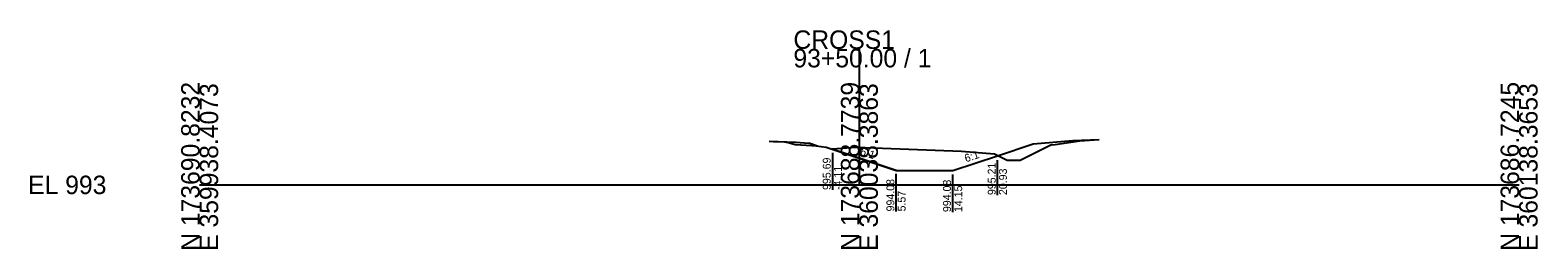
# Model space of a CAD drawing. Extents: x -26 to 1403, y -10 to 11027.
# Drawn here: x -25.7 to 202.8, y 8490.3 to 8523.5 of the extents above; entities that cross this region are included whole.
import ezdxf

# ---------------------------------------------------------------- set-up
doc = ezdxf.new("R2010")
doc.units = 0
for name, color, linetype in [('Default', 7, 'Continuous'), ('P_E_XS_Ground', 7, 'Continuous'), ('P_XS', 7, 'Continuous'), ('P_XS_EAR_CommonGrnd', 7, 'Continuous'), ('P_XS_Lane', 7, 'Continuous'), ('P_XS_Rock', 7, 'Continuous')]:
    doc.layers.add(name, color=color, linetype=linetype)

msp = doc.modelspace()

# ---------------------------------------------------------------- linework, layer by layer
at = {"layer": 'Default'}
for p, q in [((100, 8500), (100, 8520.61)), ((0, 8500), (100, 8500)), ((100, 8500), (200, 8500))]:
    msp.add_line(p, q, dxfattribs=at)
at = {"layer": 'P_E_XS_Ground'}
for p, q in [((86.35, 8506.63), (86.97, 8506.57)), ((86.97, 8506.57), (88.66, 8506.55)), ((88.66, 8506.55), (89.41, 8506.37)), ((89.41, 8506.37), (90.27, 8506.13)), ((90.27, 8506.13), (92.8, 8505.99)), ((92.8, 8505.99), (93.46, 8505.9)), ((129.12, 8506.07), (124.38, 8503.7)), ((129.12, 8506.07), (129.69, 8506.14)), ((129.69, 8506.14), (133.43, 8506.66)), ((133.43, 8506.66), (135.61, 8506.82)), ((135.61, 8506.82), (136.34, 8506.87)), ((93.46, 8505.9), (94.98, 8505.72)), ((94.98, 8505.72), (95.89, 8505.39)), ((99.5, 8505.68), (95.89, 8505.39)), ((115.5, 8505.04), (99.5, 8505.68)), ((120.5, 8504.64), (115.5, 8505.04)), ((122.38, 8503.7), (120.5, 8504.64)), ((124.38, 8503.7), (122.38, 8503.7))]:
    msp.add_line(p, q, dxfattribs=at)
at = {"layer": 'P_XS'}
for p, q in [((86.35, 8506.63), (90.35, 8506.47)), ((90.35, 8506.47), (92.35, 8506.31)), ((93.64, 8505.88), (92.35, 8506.31)), ((120.93, 8504.42), (126.35, 8506.23)), ((126.35, 8506.23), (132.35, 8506.71)), ((132.35, 8506.71), (136.35, 8506.87))]:
    msp.add_line(p, q, dxfattribs=at)
at = {"layer": 'P_XS_EAR_CommonGrnd'}
msp.add_lwpolyline([(114.15, 8502.16), (120.93, 8504.42), (120.5, 8504.64), (115.5, 8505.04), (99.5, 8505.68), (95.89, 8505.39), (105.57, 8502.16)], close=True, dxfattribs=at)
at = {"layer": 'P_XS_Lane'}
for p, q in [((105.57, 8502.16), (95.89, 8505.39)), ((114.15, 8502.16), (120.93, 8504.42)), ((105.57, 8502.16), (114.15, 8502.16))]:
    msp.add_line(p, q, dxfattribs=at)
at = {"layer": 'P_XS_Rock'}
for p, q in [((95.9, 8504.84), (95.9, 8499.23)), ((120.91, 8503.77), (120.91, 8498.46)), ((105.55, 8501.68), (105.55, 8495.97)), ((114.13, 8501.59), (114.13, 8495.88))]:
    msp.add_line(p, q, dxfattribs=at)

# ---------------------------------------------------------------- texts
at = {"layer": 'Default'}
for s, p in [('CROSS1', (90, 8520.61)), ('93+50.00 / 1', (90, 8517.81)), ('EL 993', (-26, 8498.6))]:
    msp.add_text(s, height=2.8, dxfattribs=at).set_placement(p)
for s, p in [('N 173690.8232', (0, 8490)), ('E 359938.4073', (2.8, 8490)), ('N 173688.7739', (100, 8490)), ('E 360038.3863', (102.8, 8490)), ('N 173686.7245', (200, 8490)), ('E 360138.3653', (202.8, 8490))]:
    msp.add_text(s, height=2.8, rotation=90, dxfattribs=at).set_placement(p)
at = {"layer": 'P_XS_Rock'}
for s, rotation, p in [('995.69', 90, (95.65, 8499.23)), ('6:1', 341.5651, (100.02, 8504.59)), ('6:1', 18.4349, (116.16, 8503.41)), ('-4.11', 90, (97.35, 8499.23)), ('995.21', 90, (120.66, 8498.46)), ('20.93', 90, (122.36, 8498.46)), ('994.08', 90, (105.3, 8495.98)), ('994.08', 90, (113.88, 8495.88)), ('14.15', 90, (115.58, 8495.88)), ('5.57', 90, (107, 8495.98))]:
    msp.add_text(s, height=1.2, rotation=rotation, dxfattribs=at).set_placement(p)

doc.saveas('drawing.dxf')
